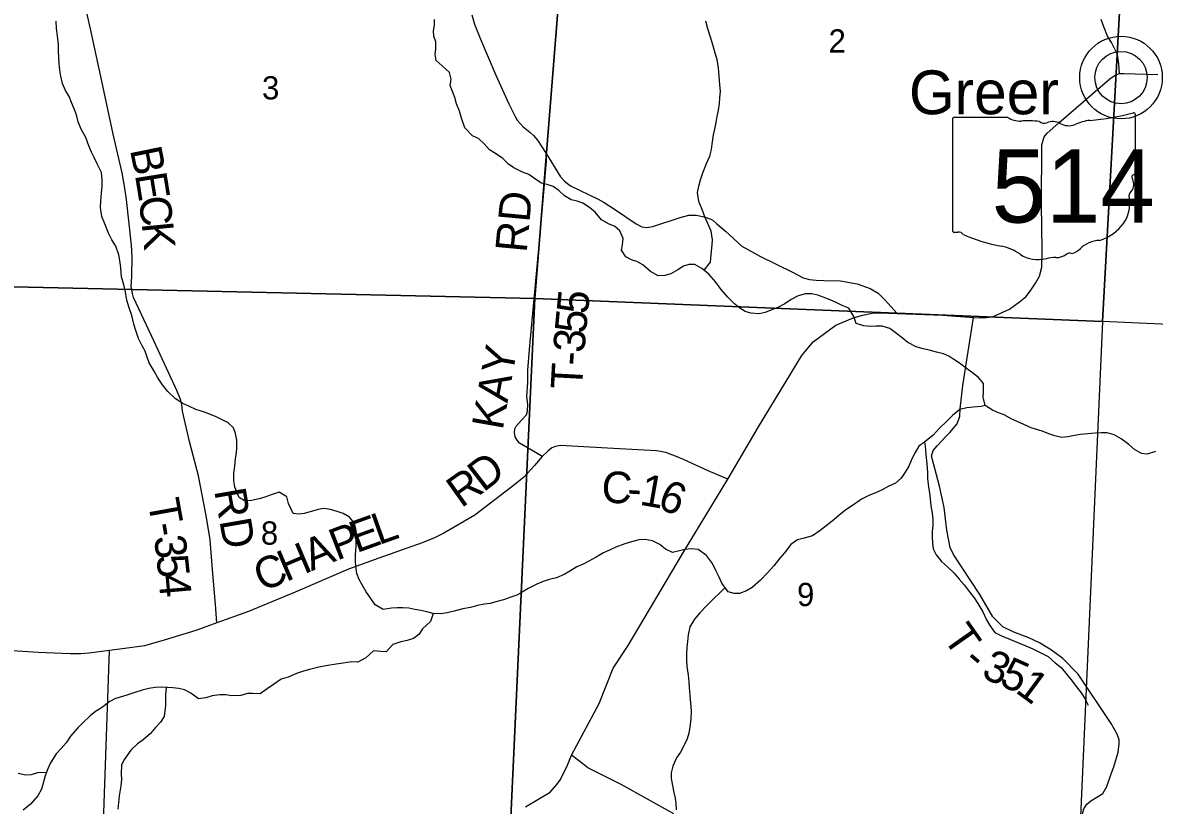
# Model space of a CAD drawing. Extents: x 1759416 to 2214760, y 252598 to 1116833.
# Drawn here: x 2041391 to 2052158, y 911921 to 919371 of the extents above; entities that cross this region are included whole.
import ezdxf

# ---------------------------------------------------------------- set-up
doc = ezdxf.new("R2010")
doc.units = 0
for name, color, linetype in [('GM_X_County_Road', 7, 'Continuous'), ('GM_X_County_Road_Text', 7, 'Continuous'), ('GM_X_Minor_River', 7, 'Continuous'), ('GM_X_Section', 7, 'Continuous'), ('GM_X_Section_Text', 7, 'Continuous'), ('GM_X_State_Location', 7, 'Continuous'), ('GM_X_State_Route', 7, 'Continuous'), ('GM_X_State_Shield', 7, 'Continuous'), ('GM_X_Township_Road', 7, 'Continuous'), ('GM_X_Township_Road_Text', 7, 'Continuous'), ('GM_X_Township_ROW', 7, 'Continuous'), ('GM_X_Unincorporated', 7, 'Continuous'), ('GM_X_Unincorporated_Location', 7, 'Continuous'), ('GM_X_Unincorporated_Text', 7, 'Continuous')]:
    doc.layers.add(name, color=color, linetype=linetype)

msp = doc.modelspace()

# ---------------------------------------------------------------- linework, layer by layer
at = {"layer": 'GM_X_County_Road'}
for points in [[(2045664, 919445), (2045690, 919357), (2045748, 919213), (2045893, 918872), (2046017, 918599), (2046077, 918477), (2046096, 918443), (2046152, 918380), (2046216, 918328), (2046250, 918298), (2046290, 918252), (2046372, 918124), (2046508, 917903), (2046546, 917863), (2046603, 917819), (2046867, 917690), (2046923, 917660), (2047023, 917595), (2047227, 917455), (2047283, 917429), (2047331, 917420), (2047387, 917430), (2047646, 917516), (2047730, 917540), (2047800, 917540), (2047876, 917523), (2047938, 917501), (2047962, 917487), (2047996, 917455), (2048077, 917385), (2048233, 917244), (2048412, 917145), (2048717, 916996), (2048816, 916943), (2048877, 916927), (2048941, 916920), (2049013, 916916), (2049171, 916915), (2049331, 916886), (2049453, 916841), (2049531, 916795), (2049595, 916734), (2049710, 916604)], [(2051828, 918886), (2051821, 918979), (2051807, 919067), (2051749, 919182), (2051711, 919242), (2051676, 919331), (2051653, 919402)], [(2048101, 915027), (2047914, 915106), (2047678, 915214), (2047619, 915240), (2047510, 915280), (2047422, 915296), (2047014, 915318), (2046506, 915345), (2046462, 915337), (2046426, 915323), (2046388, 915291), (2046334, 915241), (2046260, 915157), (2046159, 915046), (2046073, 914974), (2045694, 914684), (2045400, 914512), (2045310, 914467), (2045193, 914419), (2044779, 914273), (2044492, 914168), (2043984, 913951), (2043541, 913767), (2043239, 913660), (2043038, 913586), (2042738, 913493), (2042550, 913441), (2042362, 913413), (2042219, 913396), (2042021, 913370), (2041945, 913364), (2041845, 913365), (2041539, 913375), (2041189, 913400)]]:
    msp.add_lwpolyline(points, dxfattribs=at)
at = {"layer": 'GM_X_Minor_River'}
for points in [[(2047730, 917070), (2047678, 917052), (2047624, 917019), (2047558, 916979), (2047502, 916964), (2047436, 916961), (2047366, 917001), (2047293, 917066), (2047233, 917098), (2047183, 917113), (2047130, 917141), (2047090, 917204), (2047099, 917257), (2047103, 917317), (2047074, 917389), (2047023, 917434), (2046971, 917454), (2046897, 917493), (2046838, 917567), (2046784, 917610), (2046721, 917652), (2046667, 917671), (2046611, 917685), (2046548, 917722), (2046494, 917772), (2046439, 917811), (2046381, 917829), (2046327, 917842), (2046275, 917878), (2046206, 917925), (2046148, 917949), (2046063, 917990), (2046013, 918023), (2045961, 918077), (2045890, 918124), (2045832, 918160), (2045783, 918216), (2045727, 918267), (2045672, 918295), (2045599, 918370), (2045565, 918462), (2045546, 918528), (2045519, 918598), (2045503, 918658), (2045482, 918716), (2045460, 918773), (2045469, 918832), (2045452, 918896), (2045382, 918959), (2045325, 919009), (2045317, 919067), (2045322, 919123), (2045322, 919187), (2045303, 919241), (2045299, 919293), (2045310, 919347), (2045310, 919401)], [(2044572, 914128), (2044561, 914198), (2044557, 914248), (2044558, 914307), (2044563, 914389), (2044565, 914471), (2044564, 914537), (2044549, 914607), (2044501, 914665), (2044442, 914700), (2044384, 914718), (2044320, 914737), (2044256, 914746), (2044202, 914738), (2044150, 914721), (2044070, 914698), (2044020, 914694), (2043966, 914699), (2043921, 914795), (2043904, 914859), (2043832, 914901), (2043766, 914880), (2043696, 914855), (2043640, 914839), (2043570, 914822), (2043502, 914821), (2043450, 914851), (2043409, 914949), (2043400, 915013), (2043402, 915083), (2043409, 915151), (2043417, 915223), (2043426, 915275), (2043430, 915325), (2043429, 915398), (2043416, 915462), (2043398, 915515), (2043345, 915565), (2043295, 915589), (2043233, 915618), (2043164, 915647), (2043112, 915667), (2043038, 915690), (2042971, 915722), (2042915, 915747), (2042845, 915791), (2042774, 915860), (2042723, 915924), (2042679, 915991), (2042642, 916055), (2042595, 916133), (2042575, 916187), (2042558, 916243), (2042528, 916294), (2042495, 916366), (2042472, 916430), (2042450, 916502), (2042431, 916582), (2042406, 916656), (2042384, 916730), (2042369, 916806), (2042354, 916876), (2042333, 916950), (2042325, 917034), (2042320, 917088), (2042307, 917160), (2042279, 917244), (2042240, 917305), (2042209, 917367), (2042173, 917455), (2042146, 917525), (2042133, 917611), (2042135, 917673), (2042142, 917747), (2042147, 917813), (2042147, 917874), (2042140, 917944), (2042099, 918027), (2042073, 918087), (2042046, 918139), (2042022, 918197), (2041993, 918277), (2041948, 918357), (2041919, 918426), (2041903, 918494), (2041880, 918550), (2041856, 918612), (2041835, 918668), (2041798, 918726), (2041770, 918790), (2041755, 918862), (2041745, 918918), (2041738, 918982), (2041735, 919036), (2041733, 919102), (2041732, 919160), (2041724, 919244), (2041715, 919314), (2041710, 919384)], [(2047874, 917015), (2047934, 917090), (2047943, 917165), (2047952, 917255), (2047954, 917305), (2047941, 917387), (2047908, 917467), (2047882, 917523), (2047855, 917591), (2047826, 917670), (2047813, 917754), (2047823, 917813), (2047840, 917875), (2047864, 917941), (2047897, 918030), (2047928, 918100), (2047944, 918164), (2047951, 918215), (2047964, 918303), (2047976, 918357), (2047989, 918421), (2047999, 918478), (2048010, 918538), (2048020, 918602), (2048025, 918652), (2048029, 918720), (2048024, 918778), (2048017, 918862), (2048011, 918937), (2047998, 919019), (2047981, 919081), (2047962, 919150), (2047934, 919234), (2047909, 919312), (2047890, 919386)], [(2052170, 915290), (2052091, 915263), (2052036, 915269), (2051970, 915308), (2051914, 915356), (2051843, 915411), (2051777, 915449), (2051708, 915466), (2051652, 915468), (2051596, 915463), (2051526, 915456), (2051454, 915450), (2051398, 915441), (2051334, 915428), (2051278, 915422), (2051210, 915437), (2051154, 915457), (2051100, 915478), (2051049, 915496), (2050987, 915515), (2050915, 915547), (2050852, 915576), (2050802, 915598), (2050730, 915637), (2050676, 915658), (2050617, 915682), (2050547, 915727), (2050528, 915805), (2050534, 915855), (2050533, 915936), (2050484, 915995), (2050428, 916037), (2050371, 916080), (2050305, 916130), (2050252, 916165), (2050202, 916197), (2050152, 916218), (2050086, 916236), (2050017, 916253), (2049947, 916270), (2049893, 916284), (2049814, 916327), (2049758, 916371), (2049693, 916422), (2049641, 916460), (2049569, 916483), (2049509, 916483), (2049459, 916480), (2049393, 916484), (2049322, 916509), (2049300, 916575), (2049253, 916652), (2049187, 916680), (2049136, 916703), (2049074, 916733), (2049008, 916758), (2048955, 916776), (2048901, 916789), (2048839, 916789), (2048771, 916772), (2048704, 916735), (2048644, 916695), (2048570, 916658), (2048510, 916633), (2048457, 916613), (2048397, 916600), (2048318, 916607), (2048266, 916623), (2048216, 916652), (2048166, 916690), (2048101, 916759), (2048038, 916831), (2047985, 916901), (2047919, 916976), (2047854, 917032), (2047786, 917069), (2047730, 917070)], [(2050547, 915728), (2050511, 915719), (2050433, 915710), (2050373, 915704), (2050307, 915689), (2050237, 915632), (2050184, 915578), (2050112, 915509), (2050053, 915444), (2049971, 915379), (2049918, 915339), (2049882, 915280), (2049855, 915226), (2049821, 915149), (2049786, 915091), (2049748, 915036), (2049695, 914988), (2049627, 914955), (2049569, 914924), (2049499, 914894), (2049442, 914869), (2049372, 914834), (2049296, 914783), (2049223, 914733), (2049157, 914680), (2049092, 914625), (2049036, 914583), (2048980, 914536), (2048905, 914487), (2048825, 914464), (2048763, 914448), (2048699, 914403), (2048638, 914326), (2048594, 914274), (2048539, 914201), (2048476, 914132), (2048412, 914066), (2048331, 913995), (2048277, 913964), (2048211, 913939), (2048159, 913939), (2048105, 913954), (2048044, 914036), (2048017, 914094), (2047987, 914158), (2047956, 914223), (2047897, 914301), (2047819, 914358), (2047753, 914362), (2047691, 914355), (2047627, 914340), (2047575, 914328), (2047508, 914361), (2047452, 914403), (2047384, 914440), (2047313, 914452), (2047255, 914449), (2047184, 914430), (2047120, 914410), (2047036, 914379), (2046982, 914354), (2046916, 914324), (2046847, 914283), (2046777, 914244), (2046725, 914217), (2046665, 914193), (2046596, 914150), (2046542, 914120), (2046470, 914087), (2046400, 914070), (2046342, 914051), (2046284, 914027), (2046201, 913984), (2046145, 913949), (2046093, 913923), (2046037, 913904), (2045965, 913879), (2045892, 913857), (2045840, 913844), (2045784, 913836), (2045718, 913823), (2045652, 913806), (2045578, 913792), (2045498, 913769), (2045430, 913754), (2045370, 913745), (2045298, 913749), (2045236, 913762), (2045180, 913776), (2045123, 913787), (2045065, 913799), (2045009, 913802), (2044953, 913801), (2044899, 913797), (2044821, 913784), (2044745, 913831), (2044698, 913901), (2044661, 913953), (2044623, 914021), (2044594, 914072), (2044572, 914128)], [(2049971, 915378), (2049978, 915339), (2049985, 915261), (2049995, 915171), (2050000, 915089), (2050001, 915031), (2050009, 914949), (2050018, 914897), (2050024, 914839), (2050033, 914771), (2050044, 914701), (2050050, 914643), (2050051, 914586), (2050043, 914528), (2050044, 914476), (2050046, 914418), (2050055, 914364), (2050083, 914306), (2050132, 914241), (2050189, 914191), (2050253, 914130), (2050302, 914074), (2050350, 914020), (2050387, 913969), (2050444, 913897), (2050478, 913843), (2050527, 913762), (2050562, 913686), (2050592, 913632), (2050641, 913566), (2050705, 913535), (2050788, 913500), (2050866, 913468), (2050934, 913441), (2051003, 913412), (2051071, 913376), (2051149, 913339), (2051216, 913279), (2051271, 913234), (2051327, 913168), (2051368, 913117), (2051418, 913049), (2051461, 912991), (2051496, 912939), (2051528, 912876)], [(2048074, 913996), (2048033, 913954), (2047955, 913877), (2047904, 913828), (2047834, 913753), (2047783, 913695), (2047740, 913622), (2047722, 913546), (2047717, 913482), (2047709, 913424), (2047708, 913357), (2047708, 913303), (2047711, 913243), (2047722, 913161), (2047728, 913097), (2047731, 913043), (2047738, 912967), (2047744, 912897), (2047751, 912817), (2047748, 912743), (2047740, 912669), (2047729, 912610), (2047715, 912556), (2047684, 912494), (2047651, 912429), (2047613, 912373), (2047576, 912294), (2047560, 912232), (2047561, 912176), (2047573, 912110), (2047586, 912044), (2047599, 911990), (2047605, 911940), (2047610, 911880)], [(2045298, 913749), (2045273, 913672), (2045195, 913603), (2045162, 913549), (2045110, 913508), (2045050, 913492), (2044988, 913479), (2044914, 913454), (2044851, 913384), (2044799, 913387), (2044729, 913393), (2044657, 913326), (2044580, 913285), (2044522, 913286), (2044442, 913276), (2044374, 913265), (2044294, 913252), (2044210, 913237), (2044122, 913214), (2044062, 913200), (2043998, 913177), (2043916, 913140), (2043850, 913124), (2043779, 913071), (2043717, 913030), (2043650, 912983), (2043581, 912987), (2043529, 912986), (2043467, 912967), (2043383, 912965), (2043323, 912974), (2043267, 912974), (2043195, 912965), (2043133, 912946), (2043063, 912934), (2042991, 912989), (2042930, 913020), (2042876, 913034), (2042820, 913039), (2042768, 913043), (2042710, 913046), (2042652, 913044), (2042592, 913033), (2042528, 913018), (2042458, 912996), (2042392, 912973), (2042333, 912954), (2042275, 912938), (2042221, 912909), (2042141, 912850), (2042086, 912814), (2042034, 912775), (2041966, 912710), (2041917, 912658), (2041848, 912581), (2041806, 912516), (2041757, 912464), (2041709, 912413), (2041656, 912327), (2041632, 912270), (2041607, 912202), (2041572, 912075), (2041536, 912013), (2041465, 911934), (2041396, 911877)], [(2042758, 913043), (2042751, 912973), (2042749, 912920), (2042750, 912870), (2042744, 912820), (2042737, 912768), (2042703, 912714), (2042656, 912661), (2042608, 912606), (2042537, 912544), (2042483, 912507), (2042421, 912446), (2042360, 912362), (2042331, 912307), (2042329, 912221), (2042332, 912167), (2042326, 912107), (2042311, 912012), (2042302, 911948), (2042298, 911886)], [(2041618, 912231), (2041542, 912233), (2041473, 912213), (2041423, 912208), (2041350, 912224)]]:
    msp.add_lwpolyline(points, dxfattribs=at)
at = {"layer": 'GM_X_Section'}
for points in [[(2041384, 922209), (2044045, 922120), (2046685, 922025), (2046265, 916744), (2041016, 916863), (2041119, 919533)], [(2046685, 922025), (2051956, 921839), (2051666, 916526), (2046265, 916744)], [(2051956, 921839), (2057233, 921638), (2057057, 916281), (2051666, 916526)], [(2041016, 916863), (2046265, 916744), (2046019, 911463), (2040788, 911559)], [(2046265, 916744), (2051666, 916526), (2051430, 911243), (2046019, 911463)]]:
    msp.add_lwpolyline(points, close=True, dxfattribs=at)
at = {"layer": 'GM_X_State_Route'}
msp.add_lwpolyline([(2046174, 911909), (2046411, 912048), (2046472, 912120), (2046508, 912169), (2046576, 912304), (2046613, 912398), (2046877, 912891), (2047008, 913226), (2047153, 913443), (2047668, 914314), (2048101, 915027), (2048393, 915525), (2048805, 916203), (2048912, 916332), (2049129, 916493), (2049285, 916559), (2049380, 916587), (2049475, 916606), (2049552, 916610), (2049710, 916604), (2050146, 916587), (2050439, 916564), (2050533, 916561), (2050619, 916572), (2050780, 916644), (2050876, 916713), (2050937, 916765), (2050984, 916825), (2051026, 916890), (2051066, 916957), (2051088, 917043), (2051091, 917207), (2051083, 917637), (2051088, 918208), (2051111, 918283), (2051137, 918320), (2051248, 918418), (2051735, 918836), (2051785, 918870), (2051828, 918886), (2051868, 918886), (2052192, 918877)], dxfattribs=at)
at = {"layer": 'GM_X_State_Shield'}
for p, q in [((2050237, 918450), (2050237, 917394)), ((2050764, 918469), (2050255, 918469)), ((2051978, 917942), (2051978, 918495)), ((2051978, 917942), (2051978, 917942))]:
    msp.add_line(p, q, dxfattribs=at)
for centre, major_axis, start_param, end_param in [((2050257, 918453), (20.2, 0), 1.712693, 3.28349), ((2050886, 918591), (196, 0), 4.042523, 4.731795), ((2050950, 917875), (702, 0), 1.404758, 1.657858), ((2051110, 918458), (56.4, 0), 3.836095, 5.185415), ((2051193, 918336), (117, 0), 0.950623, 2.079405), ((2051593, 918146), (371, 0), 1.699011, 2.107814), ((2051358, 919909), (1845, 0), 4.814394, 5.042369), ((2051958, 918497), (19.4, 0), 6.141152, 7.989035), ((2051344, 918503), (141, 0), 4.081561, 5.145723), ((2051973, 917901), (30, 0), 1.883978, 3.671073), ((2051782, 917832), (180, 0), 5.934695, 6.695948), ((2051957, 917940), (20.7, 0), 5.05454, 6.418171), ((2052047, 917711), (131, 0), 2.387724, 3.262537), ((2051461, 917640), (462, 0), 5.101752, 6.440018), ((2050258, 917391), (20.3, 0), 3.00124, 4.508301), ((2050261, 917500), (155, 0), 4.665946, 4.897461), ((2050292, 917333), (56, 0), 0.519207, 1.627899), ((2050999, 918282), (1333, 0), 4.195997, 4.488961), ((2050602, 916919), (417, 0), 0.823519, 1.323587), ((2051656, 917097), (253, 0), 1.647645, 2.488434), ((2051053, 917328), (265, 0), 4.026481, 4.996735), ((2051206, 916962), (217, 0), 1.495662, 1.94098), ((2051225, 917248), (141, 0), 4.691044, 5.507374), ((2051352, 917146), (39.7, 0), 1.147584, 2.315152), ((2051336, 917291), (149, 0), 4.937069, 5.64225)]:
    msp.add_ellipse(centre, major_axis=major_axis, ratio=0.8, start_param=start_param, end_param=end_param, dxfattribs=at)
at = {"layer": 'GM_X_Township_Road'}
for points in [[(2043239, 913660), (2043225, 913832), (2043198, 914167), (2043176, 914449), (2043137, 914680), (2043063, 915058), (2042978, 915383), (2042913, 915672), (2042905, 915734), (2042895, 915778), (2042857, 915870), (2042620, 916383), (2042447, 916754), (2042437, 916794), (2042425, 916860), (2042429, 916954), (2042433, 917141), (2042428, 917253), (2042378, 917686), (2042365, 917794), (2042337, 917942), (2042254, 918309), (2042135, 918858), (2042036, 919311), (2042003, 919464)], [(2046334, 915241), (2046238, 915300), (2046118, 915370), (2046096, 915396), (2046078, 915430), (2046072, 915470), (2046074, 915504), (2046086, 915530), (2046136, 915586), (2046185, 915638), (2046195, 915674), (2046197, 915736), (2046189, 915811), (2046197, 915949), (2046198, 916063), (2046212, 916259), (2046325, 917461), (2046374, 918053), (2046372, 918124)], [(2051822, 912513), (2051824, 912545), (2051803, 912599), (2051746, 912700), (2051432, 913170), (2051289, 913318), (2051179, 913397), (2051065, 913469), (2050964, 913516), (2050821, 913571), (2050716, 913619), (2050621, 913715), (2050499, 913927), (2050246, 914309), (2050214, 914375), (2050184, 914540), (2050160, 914756), (2050113, 914959), (2050071, 915129), (2050039, 915244), (2050054, 915298), (2050091, 915344), (2050179, 915435), (2050213, 915469), (2050282, 915551), (2050306, 915627), (2050312, 915695), (2050337, 915917), (2050439, 916564)], [(2046093, 909319), (2045991, 909338), (2045358, 909515), (2044732, 909696), (2044456, 909772), (2044397, 909796), (2044266, 909853), (2043989, 910016), (2043902, 910082), (2043725, 910254), (2043391, 910566), (2043305, 910647), (2043071, 910842), (2042711, 911109), (2042225, 911469), (2042185, 911499), (2042167, 911517), (2042157, 911545), (2042162, 911763), (2042219, 913396)], [(2047588, 911840), (2047084, 912121), (2046768, 912280), (2046720, 912318), (2046613, 912398)]]:
    msp.add_lwpolyline(points, dxfattribs=at)
at = {"layer": 'GM_X_Township_ROW'}
msp.add_lwpolyline([(2051467, 911686), (2051466, 911807), (2051487, 911890), (2051516, 911933), (2051554, 911964), (2051669, 912033), (2051705, 912100), (2051748, 912222), (2051774, 912287), (2051815, 912428), (2051822, 912506), (2051822, 912513)], dxfattribs=at)
at = {"layer": 'GM_X_Unincorporated'}
for radius in [393, 249]:
    msp.add_circle((2051841, 918848), radius, dxfattribs=at)
at = {"layer": 'GM_X_Unincorporated_Location'}
msp.add_line((2051841, 918848), (2051841, 918848), dxfattribs=at)

# ---------------------------------------------------------------- texts
at = {"layer": 'GM_X_County_Road_Text'}
for s, rotation, p in [('D', 37.6641, (2045775, 914896)), ('R', 35.3757, (2045564, 914746)), ('C', 356.4461, (2046892, 914807)), ('1', 350.0158, (2047252, 914784)), ('6', 337.5018, (2047418, 914757)), ('-', 356.3604, (2047138, 914791)), ('E', 19.8568, (2044568, 914321)), ('L', 19.6331, (2044779, 914397)), ('P', 21.0955, (2044381, 914249)), ('A', 22.5577, (2044139, 914149)), ('H', 22.9676, (2043897, 914046)), ('C', 22.9705, (2043670, 913950))]:
    msp.add_text(s, height=300, rotation=rotation, dxfattribs=at).set_placement(p)
at = {"layer": 'GM_X_Section_Text'}
for s, p in [('2', (2049059, 919086)), ('3', (2043669, 918640)), ('8', (2043658, 914403)), ('9', (2048759, 913818))]:
    msp.add_text(s, height=221, rotation=0, dxfattribs=at).set_placement(p)
at = {"layer": 'GM_X_State_Location'}
msp.add_text('514', height=1, rotation=0, dxfattribs=at).set_placement((2050735, 917779))
for s in ['s', 'r']:
    msp.add_text(s, height=1, dxfattribs=at).set_placement((2051088, 917852))
at = {"layer": 'GM_X_State_Shield'}
msp.add_text('514', height=696.1, dxfattribs=at).set_placement((2050609, 917468))
at = {"layer": 'GM_X_Township_Road_Text'}
for s, rotation, p in [('B', 281.3383, (2042411, 918162)), ('E', 279.1241, (2042459, 917924)), ('C', 276.6734, (2042494, 917706)), ('RD', 84.6751, (2046186, 917176)), ('K', 275.6261, (2042523, 917462)), ('5', 84.308, (2046768, 916589)), ('5', 84.496, (2046750, 916405)), ('3', 85.1754, (2046735, 916222)), ('Y', 79.7825, (2046050, 916005)), ('-', 85.8749, (2046726, 916100)), ('T', 86.9471, (2046714, 915877)), ('A', 79.7903, (2046003, 915745)), ('K', 80.0562, (2045958, 915486)), ('RD', 279.8536, (2043213, 914917)), ('T', 280.2198, (2042580, 914815)), ('-', 279.1877, (2042620, 914596)), ('3', 277.6098, (2042639, 914476)), ('5', 275.9954, (2042663, 914296)), ('4', 275.0545, (2042682, 914113)), ('T', 305.1855, (2050139, 913517)), ('-', 320.0302, (2050325, 913272)), ('3', 336.9658, (2050502, 913142)), ('5', 336.1168, (2050671, 913070)), ('1', 323.6172, (2050825, 913004))]:
    msp.add_text(s, height=300, rotation=rotation, dxfattribs=at).set_placement(p)
at = {"layer": 'GM_X_Unincorporated_Text'}
msp.add_text('Greer', height=417, rotation=0, dxfattribs=at).set_placement((2049824, 918499))

doc.saveas('drawing.dxf')
